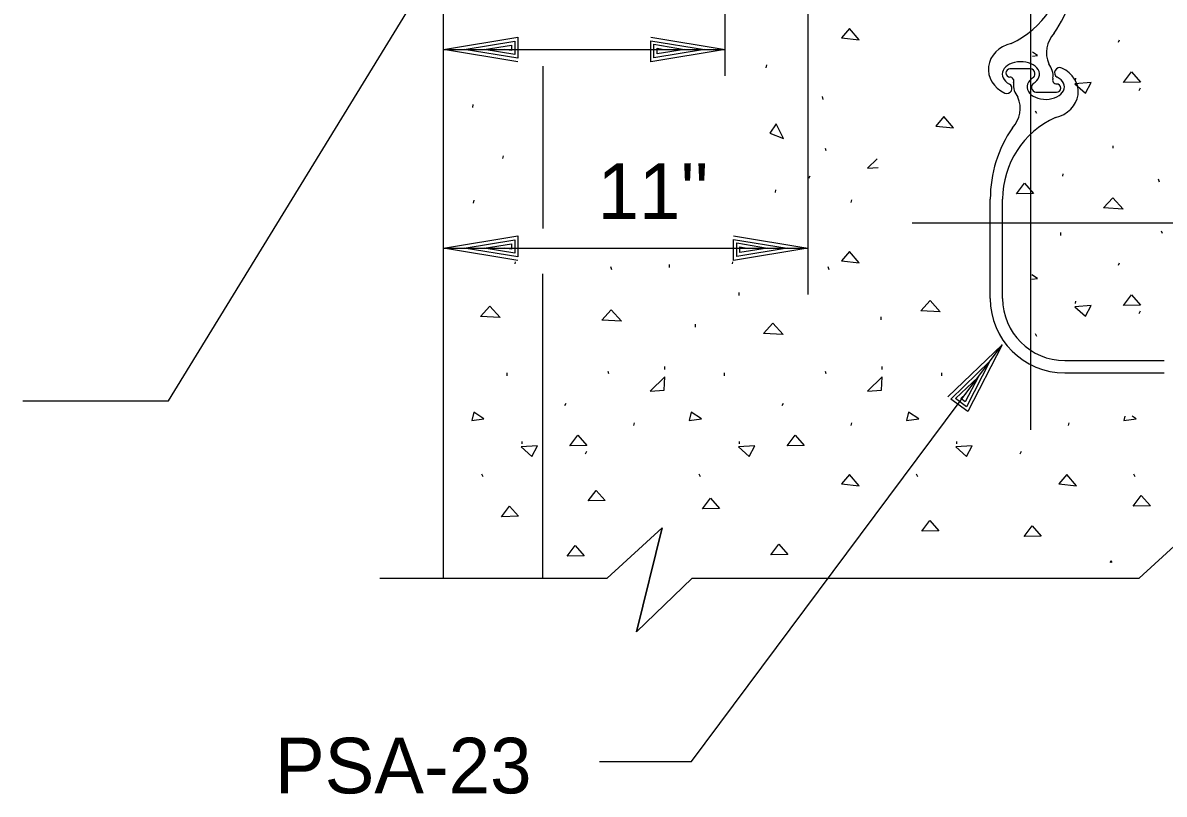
# Model space of a CAD drawing. Extents: x 22369.6 to 22428.3, y 22369.6 to 22415.
# Drawn here: x 22380.674 to 22384.482, y 22374.792 to 22377.367 of the extents above; entities that cross this region are included whole.
import ezdxf

# ---------------------------------------------------------------- set-up
doc = ezdxf.new("R2010")
doc.units = 0
for name, color, linetype in [('Level 1', 7, 'Continuous'), ('Level 10', 7, 'Continuous'), ('Level 2', 7, 'Continuous'), ('Level 4', 7, 'Continuous'), ('Level 7', 7, 'Continuous'), ('Level 8', 7, 'Continuous')]:
    doc.layers.add(name, color=color, linetype=linetype)

msp = doc.modelspace()

# ---------------------------------------------------------------- linework, layer by layer
at = {"layer": 'Level 1'}
for p, q in [((22383.0173, 22377.1897), (22383.0173, 22380.2881)), ((22384.0372, 22376.0081), (22384.0372, 22379.8661)), ((22383.2937, 22379.4663), (22383.2937, 22376.4596)), ((22381.1598, 22376.1046), (22382.8919, 22378.9306)), ((22382.0776, 22377.2779), (22383.0173, 22377.2779)), ((22382.0776, 22377.2779), (22382.0776, 22377.2779)), ((22382.1466, 22377.2779), (22382.1466, 22377.2779)), ((22382.9483, 22377.2779), (22382.9483, 22377.2779)), ((22383.0173, 22377.2779), (22383.0173, 22377.2779)), ((22383.1545, 22377.217), (22383.156, 22377.2266)), ((22384.1867, 22377.1743), (22384.1874, 22377.1816)), ((22383.3447, 22377.1112), (22383.3419, 22377.1211)), ((22384.0568, 22377.0635), (22384.0524, 22377.0723)), ((22384.3122, 22376.9479), (22384.3116, 22376.9561)), ((22384.4666, 22376.8352), (22384.4638, 22376.8451)), ((22383.6419, 22376.6994), (22386.5109, 22376.6994)), ((22382.0776, 22376.6146), (22383.2937, 22376.6146)), ((22382.0776, 22376.6146), (22382.0776, 22376.6146)), ((22382.1466, 22376.6146), (22382.1466, 22376.6146)), ((22383.2247, 22376.6146), (22383.2247, 22376.6146)), ((22383.2937, 22376.6146), (22383.2937, 22376.6146)), ((22382.3162, 22376.5618), (22382.3175, 22376.5693)), ((22383.0414, 22376.5618), (22383.0427, 22376.5693)), ((22384.1867, 22376.4299), (22384.1874, 22376.4372)), ((22384.0568, 22376.3191), (22384.0524, 22376.3279)), ((22382.9056, 22374.9006), (22383.9421, 22376.2922)), ((22383.9421, 22376.2922), (22383.9421, 22376.2922)), ((22382.816, 22376.2097), (22382.816, 22376.219)), ((22383.9009, 22376.2368), (22383.9009, 22376.2368)), ((22380.6739, 22376.1046), (22381.1598, 22376.1046)), ((22382.5514, 22375.9283), (22382.5563, 22375.9366)), ((22384.0017, 22375.9283), (22384.0067, 22375.9366)), ((22382.2097, 22375.8507), (22382.2053, 22375.8595)), ((22382.6238, 22375.513), (22382.8071, 22375.6807)), ((22382.7215, 22375.3331), (22382.8071, 22375.6807)), ((22382.8071, 22375.6807), (22382.7215, 22375.3331)), ((22384.3989, 22375.513), (22384.5822, 22375.6807)), ((22381.865, 22375.513), (22382.6238, 22375.513)), ((22382.9073, 22375.513), (22382.7215, 22375.3331)), ((22382.7215, 22375.3331), (22382.9073, 22375.513)), ((22382.9073, 22375.513), (22384.3989, 22375.513)), ((22382.5985, 22374.9006), (22382.9056, 22374.9006))]:
    msp.add_line(p, q, dxfattribs=at)
for points in [[(22382.3257, 22377.2368), (22382.0776, 22377.2779), (22382.3257, 22377.319), (22382.3257, 22377.2487), (22382.1466, 22377.2779), (22382.3151, 22377.3058), (22382.3151, 22377.2606), (22382.2129, 22377.2779), (22382.3044, 22377.2925), (22382.3044, 22377.2739), (22382.2819, 22377.2779)], [(22382.7692, 22377.319), (22383.0173, 22377.2779), (22382.7692, 22377.2368), (22382.7692, 22377.3071), (22382.9483, 22377.2779), (22382.7798, 22377.25), (22382.7798, 22377.2951), (22382.882, 22377.2779), (22382.7904, 22377.2633), (22382.7904, 22377.2819), (22382.813, 22377.2779)], [(22384.0598, 22377.2574), (22384.0433, 22377.2685)], [(22384.0433, 22377.2553), (22384.0598, 22377.2574)], [(22382.3257, 22376.5734), (22382.0776, 22376.6146), (22382.3257, 22376.6557), (22382.3257, 22376.5854), (22382.1466, 22376.6146), (22382.3151, 22376.6424), (22382.3151, 22376.5973), (22382.2129, 22376.6146), (22382.3044, 22376.6291), (22382.3044, 22376.6106), (22382.2819, 22376.6146)], [(22383.0456, 22376.6557), (22383.2937, 22376.6146), (22383.0456, 22376.5734), (22383.0456, 22376.6437), (22383.2247, 22376.6146), (22383.0562, 22376.5867), (22383.0562, 22376.6318), (22383.1584, 22376.6146), (22383.0668, 22376.6), (22383.0668, 22376.6185), (22383.0894, 22376.6146)], [(22384.0598, 22376.5129), (22384.0409, 22376.5257)], [(22383.7609, 22376.1178), (22383.9421, 22376.2922), (22383.8268, 22376.0686), (22383.7705, 22376.1106), (22383.9009, 22376.2368), (22383.8226, 22376.0851), (22383.7864, 22376.112), (22383.8612, 22376.1836), (22383.8182, 22376.1015), (22383.8033, 22376.1126), (22383.82, 22376.1283)], [(22384.3512, 22376.0532), (22384.348, 22376.0394)]]:
    msp.add_lwpolyline(points, dxfattribs=at)
at = {"layer": 'Level 10'}
for p, q in [((22382.4092, 22377.2224), (22382.4092, 22376.6798)), ((22382.4092, 22375.513), (22382.4092, 22376.5289))]:
    msp.add_line(p, q, dxfattribs=at)
at = {"layer": 'Level 2'}
for p, q in [((22384.0375, 22377.2132), (22383.9677, 22377.2132)), ((22383.9672, 22377.1855), (22383.9677, 22377.1855)), ((22384.1238, 22377.1625), (22384.1234, 22377.1625)), ((22384.0536, 22377.1349), (22384.1234, 22377.1349)), ((22383.9018, 22376.4467), (22383.9018, 22376.7784)), ((22383.9433, 22376.4467), (22383.9433, 22376.7784)), ((22384.1506, 22376.2394), (22384.4822, 22376.2394)), ((22384.1506, 22376.198), (22384.4822, 22376.198))]:
    msp.add_line(p, q, dxfattribs=at)
for centre, radius, start, end in [((22383.8501, 22377.5697), 0.2977, 294.0927, 0), ((22383.7695, 22377.5697), 0.4197, 325.4665, 0), ((22384.1823, 22377.2669), 0.0931, 135.9217, 203.707), ((22384.0481, 22377.189), 0.0635, 353.7219, 39.5759), ((22383.9677, 22377.1993), 0.0138, 90, 270), ((22384.0341, 22377.1963), 0.0172, 314.2606, 101.4897), ((22384.1337, 22377.2003), 0.0171, 65.8559, 239.9136), ((22383.9574, 22377.1477), 0.0171, 245.8559, 59.9136), ((22383.9672, 22377.1717), 0.0138, 335.7739, 89.9962), ((22384.0429, 22377.1591), 0.0635, 173.7219, 219.5759), ((22384.057, 22377.1518), 0.0172, 134.2606, 281.4897), ((22384.1238, 22377.1764), 0.0138, 155.7739, 269.9962), ((22384.1234, 22377.1487), 0.0138, 270, 90), ((22383.9088, 22377.0812), 0.0931, 315.9217, 23.707), ((22384.241, 22376.7784), 0.2977, 114.0927, 180), ((22384.3216, 22376.7784), 0.4197, 145.4665, 180), ((22384.1506, 22376.4467), 0.2488, 180, 270), ((22384.1506, 22376.4467), 0.2073, 180, 270)]:
    msp.add_arc(centre, radius, start, end, dxfattribs=at)
for centre, major_axis, ratio, start_param, end_param in [((22383.9992, 22377.2113), (-0.1036, 0), 0.866676, 4.981944, 7.363432), ((22384.004, 22377.1953), (-0.0622, 0), 0.666679, 2.289893, 7.195317), ((22384.0919, 22377.1367), (0.1036, 0), 0.866676, 4.981944, 7.363432), ((22384.087, 22377.1527), (0.0622, 0), 0.666679, 2.289893, 7.195317)]:
    msp.add_ellipse(centre, major_axis=major_axis, ratio=ratio, start_param=start_param, end_param=end_param, dxfattribs=at)
at = {"layer": 'Level 7'}
msp.add_line((22382.0776, 22375.513), (22382.0776, 22380.2497), dxfattribs=at)
at = {"layer": 'Level 8'}
for p, q in [((22384.33, 22377.3017), (22384.3336, 22377.3095)), ((22384.3985, 22377.1411), (22384.4034, 22377.1494)), ((22382.1751, 22377.0843), (22382.1766, 22377.0939)), ((22382.2758, 22376.9136), (22382.2773, 22376.9232)), ((22383.3547, 22376.9396), (22383.3519, 22376.9467)), ((22383.2962, 22376.8481), (22383.3012, 22376.8564)), ((22384.1436, 22376.8549), (22384.1449, 22376.8624)), ((22383.185, 22376.7999), (22383.1865, 22376.8095)), ((22382.1782, 22376.7651), (22382.1797, 22376.7747)), ((22383.4382, 22376.7664), (22383.4397, 22376.776)), ((22384.1374, 22376.6567), (22384.1374, 22376.6667)), ((22384.4766, 22376.6635), (22384.4737, 22376.6707)), ((22382.6392, 22376.5421), (22382.6364, 22376.5521)), ((22382.8322, 22376.5501), (22382.8322, 22376.56)), ((22383.3644, 22376.5421), (22383.3616, 22376.5521)), ((22384.33, 22376.5572), (22384.3336, 22376.565)), ((22383.0645, 22376.4563), (22383.0645, 22376.4662)), ((22384.3985, 22376.3967), (22384.4034, 22376.405)), ((22382.9189, 22376.3503), (22382.9189, 22376.3602)), ((22383.5377, 22376.3747), (22383.5377, 22376.3847)), ((22382.6295, 22376.1951), (22382.6267, 22376.2023)), ((22383.3547, 22376.1951), (22383.3519, 22376.2023)), ((22383.5412, 22376.2097), (22383.5412, 22376.219)), ((22382.2903, 22376.1883), (22382.2903, 22376.1983)), ((22383.0155, 22376.1883), (22383.0155, 22376.1983)), ((22383.7407, 22376.1883), (22383.7407, 22376.1983)), ((22382.4829, 22376.0888), (22382.4865, 22376.0966)), ((22383.2081, 22376.0888), (22383.2117, 22376.0966)), ((22382.7131, 22376.022), (22382.7145, 22376.0316)), ((22383.4382, 22376.022), (22383.4397, 22376.0316)), ((22384.1634, 22376.022), (22384.1649, 22376.0316)), ((22382.3396, 22375.9615), (22382.3403, 22375.9688)), ((22383.0648, 22375.9615), (22383.0654, 22375.9688)), ((22383.79, 22375.9615), (22383.7906, 22375.9688)), ((22382.9349, 22375.8507), (22382.9305, 22375.8595)), ((22383.6601, 22375.8507), (22383.6557, 22375.8595)), ((22384.3853, 22375.8507), (22384.3809, 22375.8595))]:
    msp.add_line(p, q, dxfattribs=at)
for points in [[(22383.4646, 22377.3097), (22383.4318, 22377.3475), (22383.4054, 22377.3162)], [(22384.3464, 22377.1673), (22384.3731, 22377.2027), (22384.4031, 22377.1687)], [(22384.1842, 22377.1635), (22384.2195, 22377.132), (22384.2384, 22377.1673)], [(22383.7797, 22377.0157), (22383.7468, 22377.0536), (22383.7205, 22377.0222)], [(22383.1667, 22376.9979), (22383.2119, 22376.9803), (22383.1881, 22377.0292)], [(22383.9893, 22376.7959), (22384.016, 22376.8312), (22384.046, 22376.7972)], [(22384.2797, 22376.7488), (22384.3112, 22376.7829), (22384.3451, 22376.7451)], [(22383.4646, 22376.5653), (22383.4318, 22376.6031), (22383.4054, 22376.5717)], [(22383.6699, 22376.4051), (22383.7014, 22376.4393), (22383.7353, 22376.4015)], [(22384.3464, 22376.4229), (22384.3731, 22376.4582), (22384.4031, 22376.4242)], [(22382.2012, 22376.3864), (22382.2327, 22376.4206), (22382.2666, 22376.3827)], [(22382.6058, 22376.3742), (22382.6374, 22376.4083), (22382.6712, 22376.3705)], [(22384.1842, 22376.4191), (22384.2195, 22376.3876), (22384.2384, 22376.4229)], [(22383.1451, 22376.3293), (22383.1767, 22376.3635), (22383.2105, 22376.3257)], [(22382.8136, 22376.1406), (22382.816, 22376.1849), (22382.7669, 22376.1369)], [(22383.5387, 22376.1406), (22383.5412, 22376.1849), (22383.4921, 22376.1369)], [(22382.1724, 22376.0394), (22382.2127, 22376.0445), (22382.1789, 22376.0673)], [(22382.8976, 22376.0394), (22382.9379, 22376.0445), (22382.9041, 22376.0673)], [(22383.6228, 22376.0394), (22383.6631, 22376.0445), (22383.6293, 22376.0673)], [(22382.4993, 22375.9545), (22382.526, 22375.9898), (22382.556, 22375.9558)], [(22383.2245, 22375.9545), (22383.2512, 22375.9898), (22383.2812, 22375.9558)], [(22382.3371, 22375.9507), (22382.3724, 22375.9192), (22382.3913, 22375.9545)], [(22383.0623, 22375.9507), (22383.0976, 22375.9192), (22383.1165, 22375.9545)], [(22383.7875, 22375.9507), (22383.8228, 22375.9192), (22383.8417, 22375.9545)], [(22383.4646, 22375.8208), (22383.4318, 22375.8586), (22383.4054, 22375.8273)], [(22384.1898, 22375.8208), (22384.157, 22375.8586), (22384.1306, 22375.8273)], [(22382.5606, 22375.7704), (22382.5873, 22375.8058), (22382.6174, 22375.7718)], [(22384.3793, 22375.7529), (22384.406, 22375.7882), (22384.4361, 22375.7542)], [(22382.2714, 22375.7179), (22382.2981, 22375.7532), (22382.3281, 22375.7192)], [(22382.9419, 22375.7441), (22382.9686, 22375.7795), (22382.9986, 22375.7455)], [(22383.6737, 22375.6696), (22383.7005, 22375.705), (22383.7305, 22375.671)], [(22384.0156, 22375.6521), (22384.0423, 22375.6874), (22384.0723, 22375.6534)], [(22382.4905, 22375.5864), (22382.5172, 22375.6217), (22382.5472, 22375.5877)], [(22383.1698, 22375.5908), (22383.1965, 22375.6261), (22383.2265, 22375.5921)]]:
    msp.add_lwpolyline(points, close=True, dxfattribs=at)
for points in [[(22383.5244, 22376.9128), (22383.4921, 22376.8814)], [(22383.4921, 22376.8814), (22383.5282, 22376.8842)], [(22384.0409, 22376.5105), (22384.0598, 22376.5129)], [(22384.3883, 22376.0445), (22384.3755, 22376.0532)], [(22384.348, 22376.0394), (22384.3883, 22376.0445)], [(22384.3054, 22375.5711), (22384.3013, 22375.5651)], [(22384.3084, 22375.5649), (22384.3054, 22375.5711)]]:
    msp.add_lwpolyline(points, dxfattribs=at)

# ---------------------------------------------------------------- texts
at = {"layer": 'Level 4'}
for s, p in [("11''", (22382.5918, 22376.7121)), ('PSA-23', (22381.5154, 22374.7942))]:
    msp.add_text(s, height=0.1857, dxfattribs=at).set_placement(p)

doc.saveas('drawing.dxf')
